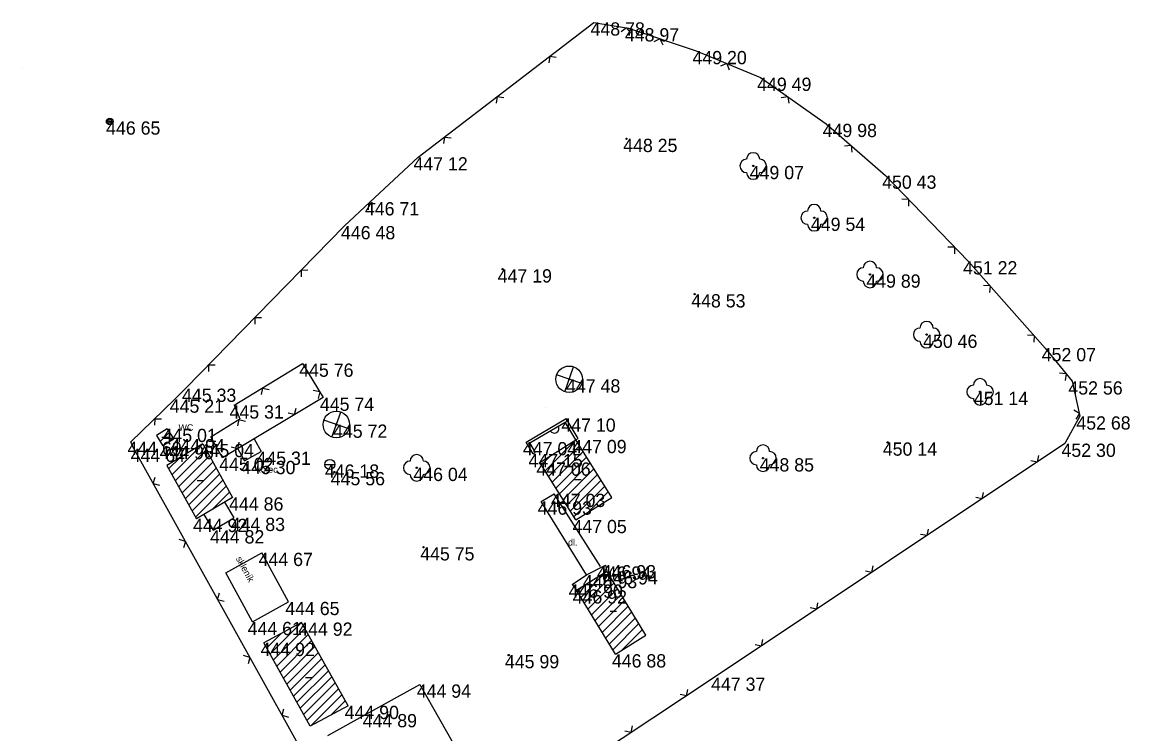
# Model space of a CAD drawing. Extents: x -554123 to -553118, y -1076825 to -1073672.
# Drawn here: x -553887.3 to -553803.8, y -1073725.5 to -1073671.8 of the extents above; entities that cross this region are included whole.
import ezdxf

# ---------------------------------------------------------------- set-up
doc = ezdxf.new("R2010")
doc.units = 0
for name, color, linetype in [('1', 7, 'Continuous'), ('12', 7, 'Continuous'), ('14', 7, 'Continuous'), ('17', 7, 'Continuous'), ('18', 7, 'Continuous'), ('20', 7, 'Continuous'), ('32', 7, 'Continuous'), ('34', 7, 'Continuous'), ('47', 7, 'Continuous'), ('52', 7, 'Continuous'), ('6', 7, 'Continuous')]:
    doc.layers.add(name, color=color, linetype=linetype)

# ---------------------------------------------------------------- blocks, each defined once
blk = doc.blocks.new('POINT_DISPLAY')
blk.add_line((0, 0), (0, 0))
blk = doc.blocks.new('SLB')
at = {"layer": '20'}
for radius in [0.25, 0.158, 0.05]:
    blk.add_circle((0, 0), radius, dxfattribs=at)
blk = doc.blocks.new('ST')
at = {"layer": '1'}
blk.add_line((-0.375, 0), (0.375, 0), dxfattribs=at)
blk.add_circle((0, 0), 0.375, dxfattribs=at)
blk = doc.blocks.new('T')
at = {"layer": '6'}
blk.add_circle((0, 0), 0.05, dxfattribs=at)
blk = doc.blocks.new('STJ')
at = {"layer": '34'}
for p, q in [((-0.327, -0.945), (0.327, 0.945)), ((0.945, -0.327), (-0.945, 0.327))]:
    blk.add_line(p, q, dxfattribs=at)
for radius in [1, 0.0496]:
    blk.add_circle((0, 0), radius, dxfattribs=at)
blk = doc.blocks.new('STL')
at = {"layer": '34'}
blk.add_circle((0, 0), 0.05, dxfattribs=at)
for centre, start, end in [((0, 0.5), 0, 180), ((-0.5, 0), 90, 270), ((0.5, 0), 270, 90), ((0, -0.5), 180, 0)]:
    blk.add_arc(centre, 0.5, start, end, dxfattribs=at)
blk = doc.blocks.new('BN')
at = {"layer": '47'}
blk.add_line((-0.25, 0), (0.25, 0), dxfattribs=at)

msp = doc.modelspace()

# ---------------------------------------------------------------- linework, layer by layer
at = {"layer": '12'}
for p, q in [((-553857.47, -1073681.97), (-553844.23, -1073671.8)), ((-553844.23, -1073671.8), (-553841.63, -1073672.24)), ((-553841.765, -1073672.217), (-553842.173, -1073672.507)), ((-553841.765, -1073672.217), (-553841.475, -1073672.625)), ((-553841.63, -1073672.24), (-553836.53, -1073673.96)), ((-553839.261, -1073673.039), (-553839.71, -1073673.261)), ((-553839.261, -1073673.039), (-553839.039, -1073673.487)), ((-553836.53, -1073673.96), (-553831.66, -1073675.97)), ((-553847.557, -1073674.355), (-553847.622, -1073674.852)), ((-553847.557, -1073674.355), (-553847.061, -1073674.421)), ((-553834.219, -1073674.914), (-553834.681, -1073675.106)), ((-553834.219, -1073674.914), (-553834.027, -1073675.376)), ((-553831.66, -1073675.97), (-553826.71, -1073679.45)), ((-553851.522, -1073677.401), (-553851.587, -1073677.898)), ((-553851.522, -1073677.401), (-553851.026, -1073677.466)), ((-553829.615, -1073677.408), (-553830.108, -1073677.494)), ((-553829.615, -1073677.408), (-553829.529, -1073677.901)), ((-553826.71, -1073679.45), (-553822.25, -1073683.35)), ((-553855.487, -1073680.447), (-553855.552, -1073680.943)), ((-553855.487, -1073680.447), (-553854.991, -1073680.512)), ((-553824.828, -1073681.096), (-553825.328, -1073681.129)), ((-553824.828, -1073681.096), (-553824.795, -1073681.595)), ((-553861.12, -1073685.36), (-553857.47, -1073681.97)), ((-553822.25, -1073683.35), (-553816.03, -1073689.81)), ((-553863.04, -1073687.16), (-553861.12, -1073685.36)), ((-553861.216, -1073685.45), (-553861.232, -1073685.951)), ((-553861.216, -1073685.45), (-553860.716, -1073685.466)), ((-553820.516, -1073685.151), (-553821.017, -1073685.141)), ((-553820.516, -1073685.151), (-553820.525, -1073685.651)), ((-553875.02, -1073699.42), (-553863.04, -1073687.16)), ((-553817.048, -1073688.753), (-553817.549, -1073688.743)), ((-553817.048, -1073688.753), (-553817.057, -1073689.253)), ((-553816.03, -1073689.81), (-553810.21, -1073696.36)), ((-553866.284, -1073690.48), (-553865.783, -1073690.474)), ((-553866.284, -1073690.48), (-553866.278, -1073690.98)), ((-553814.369, -1073691.679), (-553814.869, -1073691.649)), ((-553814.369, -1073691.679), (-553814.399, -1073692.179)), ((-553869.778, -1073694.056), (-553869.278, -1073694.05)), ((-553869.778, -1073694.056), (-553869.773, -1073694.556)), ((-553811.048, -1073695.417), (-553811.548, -1073695.387)), ((-553811.048, -1073695.417), (-553811.078, -1073695.916)), ((-553810.21, -1073696.36), (-553808.19, -1073698.87)), ((-553873.273, -1073697.632), (-553872.772, -1073697.626)), ((-553873.273, -1073697.632), (-553873.267, -1073698.133)), ((-553871.33, -1073700.68), (-553866.18, -1073697.53)), ((-553866.18, -1073697.53), (-553864.64, -1073700.1)), ((-553808.643, -1073698.308), (-553809.14, -1073698.254)), ((-553808.643, -1073698.308), (-553808.696, -1073698.805)), ((-553808.19, -1073698.87), (-553807.59, -1073701.51)), ((-553875.84, -1073700.24), (-553875.02, -1073699.42)), ((-553869.197, -1073699.376), (-553869.315, -1073699.862)), ((-553869.197, -1073699.376), (-553868.711, -1073699.493)), ((-553864.895, -1073699.674), (-553865.381, -1073699.553)), ((-553864.895, -1073699.674), (-553865.017, -1073700.16)), ((-553879.12, -1073703.43), (-553875.84, -1073700.24)), ((-553864.64, -1073700.1), (-553872.22, -1073704.64)), ((-553871.33, -1073700.68), (-553870.91, -1073701.71)), ((-553866.785, -1073701.385), (-553867.27, -1073701.263)), ((-553866.785, -1073701.385), (-553866.663, -1073700.899)), ((-553807.59, -1073701.51), (-553808.72, -1073703.57)), ((-553807.636, -1073701.308), (-553808.06, -1073701.041)), ((-553807.636, -1073701.308), (-553807.903, -1073701.731)), ((-553877.328, -1073701.687), (-553877.335, -1073702.188)), ((-553877.328, -1073701.687), (-553876.827, -1073701.694)), ((-553873.11, -1073703.06), (-553870.91, -1073701.71)), ((-553870.979, -1073701.752), (-553871.096, -1073702.239)), ((-553870.979, -1073701.752), (-553870.492, -1073701.869)), ((-553849.34, -1073703.45), (-553846.32, -1073701.67)), ((-553849.064, -1073703.52), (-553846.39, -1073701.944)), ((-553845.595, -1073703.293), (-553846.39, -1073701.944)), ((-553846.218, -1073701.842), (-553846.32, -1073701.67)), ((-553845.423, -1073703.192), (-553846.32, -1073701.67)), ((-553872.22, -1073704.64), (-553873.11, -1073703.06)), ((-553845.595, -1073703.293), (-553845.423, -1073703.192)), ((-553878.9, -1073703.95), (-553879.12, -1073703.43)), ((-553878.9, -1073703.95), (-553863.75, -1073731.22)), ((-553871.074, -1073703.954), (-553871.56, -1073703.832)), ((-553871.074, -1073703.954), (-553870.952, -1073703.468)), ((-553848.8, -1073704.35), (-553849.34, -1073703.45)), ((-553848.628, -1073704.247), (-553849.064, -1073703.52)), ((-553808.72, -1073703.57), (-553835.15, -1073721.21)), ((-553848.8, -1073704.35), (-553848.628, -1073704.247)), ((-553810.799, -1073704.958), (-553811.29, -1073704.86)), ((-553810.799, -1073704.958), (-553810.701, -1073704.467)), ((-553877.443, -1073706.572), (-553877.306, -1073706.091)), ((-553877.443, -1073706.572), (-553876.962, -1073706.71)), ((-553814.958, -1073707.734), (-553814.86, -1073707.243)), ((-553814.958, -1073707.734), (-553815.449, -1073707.636)), ((-553819.117, -1073710.509), (-553819.608, -1073710.411)), ((-553819.117, -1073710.509), (-553819.019, -1073710.018)), ((-553875.015, -1073710.943), (-553875.496, -1073710.806)), ((-553875.015, -1073710.943), (-553875.152, -1073711.425)), ((-553823.276, -1073713.285), (-553823.767, -1073713.187)), ((-553823.276, -1073713.285), (-553823.178, -1073712.794)), ((-553872.587, -1073715.314), (-553872.449, -1073714.833)), ((-553872.587, -1073715.314), (-553872.105, -1073715.452)), ((-553827.435, -1073716.061), (-553827.337, -1073715.57)), ((-553827.435, -1073716.061), (-553827.926, -1073715.963)), ((-553831.593, -1073718.836), (-553832.084, -1073718.738)), ((-553831.593, -1073718.836), (-553831.495, -1073718.345)), ((-553870.158, -1073719.685), (-553870.64, -1073719.547)), ((-553870.158, -1073719.685), (-553870.296, -1073720.166)), ((-553835.15, -1073721.21), (-553850.11, -1073731.1)), ((-553837.235, -1073722.589), (-553837.135, -1073722.098)), ((-553837.235, -1073722.589), (-553837.726, -1073722.489)), ((-553867.73, -1073724.056), (-553867.593, -1073723.574)), ((-553867.73, -1073724.056), (-553867.249, -1073724.193)), ((-553841.406, -1073725.346), (-553841.306, -1073724.856)), ((-553841.406, -1073725.346), (-553841.897, -1073725.246))]:
    msp.add_line(p, q, dxfattribs=at)
msp.add_arc((-553847.212, -1073702.428), 0.35, 210.51421, 30.51421, dxfattribs=at)
at = {"layer": '14'}
for p, q in [((-553876.38, -1073702.45), (-553877.19, -1073702.96)), ((-553877.19, -1073702.96), (-553876.71, -1073703.74)), ((-553875.9, -1073703.23), (-553876.71, -1073703.74)), ((-553876.38, -1073702.45), (-553875.9, -1073703.23)), ((-553873.7, -1073703.59), (-553876.42, -1073705.21)), ((-553873.7, -1073703.59), (-553871.47, -1073707.62)), ((-553848.3, -1073704.99), (-553845.59, -1073703.29)), ((-553842.88, -1073707.62), (-553845.59, -1073703.29)), ((-553876.42, -1073705.21), (-553874.19, -1073709.24)), ((-553845.59, -1073709.32), (-553848.3, -1073704.99)), ((-553871.47, -1073707.62), (-553874.19, -1073709.24)), ((-553845.59, -1073709.32), (-553842.88, -1073707.62)), ((-553845.55, -1073714.63), (-553843.24, -1073713.19)), ((-553840.3, -1073718.01), (-553843.24, -1073713.19)), ((-553842.61, -1073719.45), (-553845.55, -1073714.63)), ((-553866.26, -1073717.06), (-553869.1, -1073718.59)), ((-553862.76, -1073723.34), (-553866.26, -1073717.06)), ((-553842.61, -1073719.45), (-553840.3, -1073718.01)), ((-553865.6, -1073724.87), (-553869.1, -1073718.59)), ((-553862.76, -1073723.34), (-553865.6, -1073724.87))]:
    msp.add_line(p, q, dxfattribs=at)
at = {"layer": '17'}
for p, q in [((-553848.19, -1073707.93), (-553847.21, -1073707.35)), ((-553843.74, -1073712.83), (-553847.21, -1073707.35)), ((-553844.78, -1073713.47), (-553848.19, -1073707.93)), ((-553861.4, -1073723.96), (-553857.34, -1073721.73)), ((-553857.34, -1073721.73), (-553854.38, -1073726.95)), ((-553864.29, -1073725.58), (-553861.4, -1073723.96))]:
    msp.add_line(p, q, dxfattribs=at)
at = {"layer": '18'}
for p, q in [((-553869.833, -1073703.21), (-553869.3, -1073704.17)), ((-553871.071, -1073703.952), (-553870.56, -1073704.87)), ((-553870.56, -1073704.87), (-553869.3, -1073704.17)), ((-553872.066, -1073707.975), (-553871.36, -1073709.16)), ((-553873.631, -1073708.907), (-553872.92, -1073710.1)), ((-553872.92, -1073710.1), (-553871.36, -1073709.16)), ((-553871.98, -1073713.31), (-553869.25, -1073711.8)), ((-553867.24, -1073715.5), (-553869.25, -1073711.8)), ((-553844.78, -1073713.47), (-553843.36, -1073712.73)), ((-553843.36, -1073712.73), (-553843.24, -1073713.19)), ((-553869.97, -1073717.01), (-553871.98, -1073713.31)), ((-553845.86, -1073714.19), (-553844.78, -1073713.47)), ((-553845.86, -1073714.19), (-553845.55, -1073714.63)), ((-553869.97, -1073717.01), (-553867.24, -1073715.5))]:
    msp.add_line(p, q, dxfattribs=at)
at = {"layer": '32'}
for p, q in [((-553876.921, -1073703.398), (-553876.225, -1073702.702)), ((-553876.294, -1073703.478), (-553875.956, -1073703.14)), ((-553876.028, -1073705.918), (-553873.7, -1073703.59)), ((-553875.776, -1073706.373), (-553873.448, -1073704.045)), ((-553847.911, -1073705.611), (-553845.59, -1073703.29)), ((-553847.639, -1073706.046), (-553845.318, -1073703.725)), ((-553876.28, -1073705.463), (-553875.448, -1073704.631)), ((-553875.524, -1073706.829), (-553873.196, -1073704.5)), ((-553848.183, -1073705.176), (-553847.487, -1073704.48)), ((-553847.367, -1073706.481), (-553845.046, -1073704.16)), ((-553847.095, -1073706.916), (-553844.773, -1073704.595)), ((-553875.272, -1073707.284), (-553872.944, -1073704.956)), ((-553875.021, -1073707.739), (-553872.692, -1073705.411)), ((-553846.822, -1073707.351), (-553844.501, -1073705.03)), ((-553846.55, -1073707.786), (-553844.229, -1073705.465)), ((-553874.769, -1073708.194), (-553872.441, -1073705.866)), ((-553874.517, -1073708.649), (-553872.189, -1073706.321)), ((-553846.278, -1073708.221), (-553843.957, -1073705.899)), ((-553846.006, -1073708.656), (-553843.685, -1073706.334)), ((-553874.265, -1073709.105), (-553871.937, -1073706.776)), ((-553872.961, -1073708.508), (-553871.685, -1073707.232)), ((-553845.734, -1073709.09), (-553843.412, -1073706.769)), ((-553844.694, -1073708.758), (-553843.14, -1073707.204)), ((-553845.22, -1073715.17), (-553843.24, -1073713.19)), ((-553844.952, -1073715.61), (-553842.972, -1073713.629)), ((-553844.685, -1073716.049), (-553842.704, -1073714.068)), ((-553845.488, -1073714.731), (-553845.117, -1073714.36)), ((-553844.417, -1073716.488), (-553842.436, -1073714.508)), ((-553844.149, -1073716.927), (-553842.168, -1073714.947)), ((-553843.881, -1073717.366), (-553841.901, -1073715.386)), ((-553843.613, -1073717.806), (-553841.633, -1073715.825)), ((-553843.345, -1073718.245), (-553841.365, -1073716.264)), ((-553868.631, -1073719.431), (-553866.26, -1073717.06)), ((-553843.077, -1073718.684), (-553841.097, -1073716.704)), ((-553842.809, -1073719.123), (-553840.829, -1073717.143)), ((-553868.884, -1073718.977), (-553867.793, -1073717.886)), ((-553868.378, -1073719.885), (-553866.007, -1073717.514)), ((-553868.125, -1073720.339), (-553865.754, -1073717.968)), ((-553842.129, -1073719.15), (-553840.561, -1073717.582)), ((-553867.872, -1073720.793), (-553865.501, -1073718.422)), ((-553867.619, -1073721.247), (-553865.248, -1073718.876)), ((-553867.366, -1073721.701), (-553864.995, -1073719.33)), ((-553867.113, -1073722.155), (-553864.742, -1073719.784)), ((-553866.86, -1073722.61), (-553864.489, -1073720.238)), ((-553866.607, -1073723.064), (-553864.236, -1073720.692)), ((-553866.354, -1073723.518), (-553863.983, -1073721.146)), ((-553866.101, -1073723.972), (-553863.729, -1073721.601)), ((-553865.848, -1073724.426), (-553863.476, -1073722.055)), ((-553865.567, -1073724.852), (-553863.223, -1073722.509)), ((-553864.034, -1073724.026), (-553862.97, -1073722.963))]:
    msp.add_line(p, q, dxfattribs=at)

# ---------------------------------------------------------------- block references
at = {"layer": '1'}
for name, p in [('POINT_DISPLAY', (-553844.23, -1073671.8)), ('POINT_DISPLAY', (-553841.63, -1073672.24)), ('POINT_DISPLAY', (-553836.53, -1073673.96)), ('POINT_DISPLAY', (-553887.32, -1073675.17)), ('POINT_DISPLAY', (-553831.66, -1073675.97)), ('POINT_DISPLAY', (-553880.72, -1073679.27)), ('POINT_DISPLAY', (-553826.71, -1073679.45)), ('POINT_DISPLAY', (-553841.77, -1073680.58)), ('POINT_DISPLAY', (-553857.47, -1073681.97)), ('POINT_DISPLAY', (-553832.22, -1073682.63)), ('POINT_DISPLAY', (-553822.25, -1073683.35)), ('POINT_DISPLAY', (-553861.12, -1073685.36)), ('POINT_DISPLAY', (-553827.62, -1073686.53)), ('POINT_DISPLAY', (-553863.04, -1073687.16)), ('POINT_DISPLAY', (-553816.03, -1073689.81)), ('POINT_DISPLAY', (-553851.11, -1073690.42)), ('POINT_DISPLAY', (-553823.42, -1073690.81)), ('POINT_DISPLAY', (-553836.64, -1073692.3)), ('POINT_DISPLAY', (-553819.15, -1073695.35)), ('POINT_DISPLAY', (-553810.21, -1073696.36)), ('POINT_DISPLAY', (-553866.18, -1073697.53)), ('POINT_DISPLAY', (-553846.09, -1073698.72)), ('POINT_DISPLAY', (-553808.19, -1073698.87)), ('POINT_DISPLAY', (-553875.02, -1073699.42)), ('POINT_DISPLAY', (-553815.12, -1073699.66)), ('POINT_DISPLAY', (-553875.84, -1073700.24)), ('POINT_DISPLAY', (-553871.33, -1073700.68)), ('POINT_DISPLAY', (-553864.64, -1073700.1)), ('POINT_DISPLAY', (-553847.87, -1073700.82)), ('POINT_DISPLAY', (-553807.59, -1073701.51)), ('POINT_DISPLAY', (-553870.91, -1073701.71)), ('POINT_DISPLAY', (-553863.64, -1073702.13)), ('POINT_DISPLAY', (-553846.32, -1073701.67)), ('POINT_DISPLAY', (-553876.38, -1073702.45)), ('POINT_DISPLAY', (-553875.9, -1073703.23)), ('POINT_DISPLAY', (-553873.11, -1073703.06)), ('POINT_DISPLAY', (-553879.12, -1073703.43)), ('POINT_DISPLAY', (-553878.9, -1073703.95)), ('POINT_DISPLAY', (-553876.71, -1073703.74)), ('POINT_DISPLAY', (-553873.7, -1073703.59)), ('POINT_DISPLAY', (-553849.34, -1073703.45)), ('POINT_DISPLAY', (-553845.59, -1073703.29)), ('POINT_DISPLAY', (-553822.09, -1073703.48)), ('POINT_DISPLAY', (-553808.72, -1073703.57)), ('POINT_DISPLAY', (-553872.22, -1073704.64)), ('POINT_DISPLAY', (-553870.56, -1073704.87)), ('POINT_DISPLAY', (-553869.3, -1073704.17)), ('ST', (-553864.13, -1073705.14)), ('POINT_DISPLAY', (-553848.8, -1073704.35)), ('POINT_DISPLAY', (-553831.48, -1073704.67)), ('POINT_DISPLAY', (-553864.13, -1073705.14)), ('POINT_DISPLAY', (-553863.8, -1073705.71)), ('POINT_DISPLAY', (-553857.58, -1073705.39)), ('POINT_DISPLAY', (-553848.3, -1073704.99)), ('POINT_DISPLAY', (-553847.21, -1073707.35)), ('POINT_DISPLAY', (-553871.47, -1073707.62)), ('POINT_DISPLAY', (-553848.19, -1073707.93)), ('POINT_DISPLAY', (-553874.19, -1073709.24)), ('POINT_DISPLAY', (-553871.36, -1073709.16)), ('POINT_DISPLAY', (-553845.59, -1073709.32)), ('POINT_DISPLAY', (-553872.92, -1073710.1)), ('POINT_DISPLAY', (-553857.07, -1073711.38)), ('POINT_DISPLAY', (-553869.25, -1073711.8)), ('POINT_DISPLAY', (-553843.74, -1073712.83)), ('POINT_DISPLAY', (-553843.36, -1073712.73)), ('POINT_DISPLAY', (-553843.24, -1073713.19)), ('POINT_DISPLAY', (-553844.78, -1073713.47)), ('POINT_DISPLAY', (-553845.86, -1073714.19)), ('POINT_DISPLAY', (-553845.55, -1073714.63)), ('POINT_DISPLAY', (-553867.24, -1073715.5)), ('POINT_DISPLAY', (-553869.97, -1073717.01)), ('POINT_DISPLAY', (-553866.26, -1073717.06)), ('POINT_DISPLAY', (-553869.1, -1073718.59)), ('POINT_DISPLAY', (-553850.66, -1073719.51)), ('POINT_DISPLAY', (-553842.61, -1073719.45)), ('POINT_DISPLAY', (-553835.15, -1073721.21)), ('POINT_DISPLAY', (-553857.34, -1073721.73)), ('POINT_DISPLAY', (-553862.76, -1073723.34)), ('POINT_DISPLAY', (-553861.4, -1073723.96))]:
    msp.add_blockref(name, p, dxfattribs=at)
at = {"layer": '20'}
msp.add_blockref('SLB', (-553880.72, -1073679.27), dxfattribs=at)
at = {"layer": '32'}
for p in [(-553877.19, -1073702.96), (-553873.7, -1073703.59), (-553845.59, -1073703.29), (-553843.24, -1073713.19), (-553866.26, -1073717.06)]:
    msp.add_blockref('POINT_DISPLAY', p, dxfattribs=at)
at = {"layer": '34'}
for name, p in [('STL', (-553832.22, -1073682.63)), ('STL', (-553827.62, -1073686.53)), ('STL', (-553823.42, -1073690.81)), ('STL', (-553819.15, -1073695.35)), ('STJ', (-553846.09, -1073698.72)), ('STL', (-553815.12, -1073699.66)), ('STJ', (-553863.64, -1073702.13)), ('STL', (-553831.48, -1073704.67)), ('STL', (-553857.58, -1073705.39))]:
    msp.add_blockref(name, p, dxfattribs=at)
at = {"layer": '47'}
for p in [(-553876.548, -1073703.088), (-553873.882, -1073706.345), (-553845.427, -1073706.27), (-553842.761, -1073716.198), (-553865.709, -1073721.21)]:
    msp.add_blockref('BN', p, dxfattribs=at)
at = {"layer": '6'}
for p in [(-553841.77, -1073680.58), (-553851.11, -1073690.42), (-553836.64, -1073692.3), (-553822.09, -1073703.48), (-553863.8, -1073705.71), (-553857.07, -1073711.38), (-553850.66, -1073719.51)]:
    msp.add_blockref('T', p, dxfattribs=at)

# ---------------------------------------------------------------- texts
at = {"layer": '52'}
for s, p in [('WC', (-553875.534, -1073702.608)), ('kotec', (-553869.659, -1073705.768)), ('dl.', (-553846.172, -1073711.262))]:
    msp.add_text(s, height=0.5, dxfattribs=at).set_placement(p)
msp.add_text('skleník', height=0.5, rotation=298.51272, dxfattribs=at).set_placement((-553871.227, -1073712.24))
at = {"layer": '6'}
for s, p in [('448 78 ', (-553844.478, -1073672.8)), ('448 97 ', (-553841.89, -1073673.24)), ('449 20 ', (-553836.794, -1073674.96)), ('449 49 ', (-553831.922, -1073676.97)), ('446 65 ', (-553880.994, -1073680.27)), ('449 98 ', (-553826.984, -1073680.45)), ('448 25 ', (-553842.02, -1073681.58)), ('447 12 ', (-553857.827, -1073682.97)), ('449 07 ', (-553832.482, -1073683.63)), ('450 43 ', (-553822.502, -1073684.35)), ('446 71 ', (-553861.487, -1073686.36)), ('449 54 ', (-553827.87, -1073687.53)), ('446 48 ', (-553863.29, -1073688.16)), ('451 22 ', (-553816.401, -1073690.81)), ('447 19 ', (-553851.479, -1073691.42)), ('449 89 ', (-553823.694, -1073691.81)), ('448 53 ', (-553836.89, -1073693.3)), ('450 46 ', (-553819.414, -1073696.35)), ('452 07 ', (-553810.472, -1073697.36)), ('445 76 ', (-553866.44, -1073698.53)), ('447 48 ', (-553846.326, -1073699.72)), ('452 56 ', (-553808.464, -1073699.87)), ('445 33 ', (-553875.27, -1073700.42)), ('451 14 ', (-553815.588, -1073700.66)), ('445 21 ', (-553876.197, -1073701.24)), ('445 31 ', (-553871.687, -1073701.68)), ('445 74 ', (-553864.876, -1073701.1)), ('452 68 ', (-553807.864, -1073702.51)), ('445 72 ', (-553863.888, -1073703.13)), ('447 10 ', (-553846.679, -1073702.67)), ('445 01 ', (-553876.739, -1073703.45)), ('444 94 ', (-553876.138, -1073704.23)), ('444 69 ', (-553879.382, -1073704.43)), ('444 64 ', (-553879.138, -1073704.95)), ('444 90 ', (-553876.962, -1073704.74)), ('445 04 ', (-553873.94, -1073704.59)), ('447 04 ', (-553849.578, -1073704.45)), ('447 09 ', (-553845.852, -1073704.29)), ('450 14 ', (-553822.451, -1073704.48)), ('452 30 ', (-553808.984, -1073704.57)), ('445 02 ', (-553872.472, -1073705.64)), ('445 30 ', (-553870.812, -1073705.87)), ('445 31 ', (-553869.657, -1073705.17)), ('447 15 ', (-553849.157, -1073705.35)), ('448 85 ', (-553831.73, -1073705.67)), ('446 18 ', (-553864.501, -1073706.14)), ('445 56 ', (-553864.062, -1073706.71)), ('446 04 ', (-553857.832, -1073706.39)), ('447 06 ', (-553848.562, -1073705.99)), ('447 03 ', (-553847.46, -1073708.35)), ('444 86 ', (-553871.72, -1073708.62)), ('446 93 ', (-553848.464, -1073708.93)), ('444 92 ', (-553874.44, -1073710.24)), ('444 83 ', (-553871.598, -1073710.16)), ('447 05 ', (-553845.84, -1073710.32)), ('444 82 ', (-553873.158, -1073711.1)), ('445 75 ', (-553857.318, -1073712.38)), ('444 67 ', (-553869.498, -1073712.8)), ('446 94 ', (-553844.002, -1073713.83)), ('446 93 ', (-553843.634, -1073713.73)), ('446 94 ', (-553843.502, -1073714.19)), ('446 93 ', (-553845.054, -1073714.47)), ('446 90 ', (-553846.136, -1073715.19)), ('446 92 ', (-553845.824, -1073715.63)), ('444 65 ', (-553867.49, -1073716.5)), ('444 61 ', (-553870.327, -1073718.01)), ('444 92 ', (-553866.51, -1073718.06)), ('444 92 ', (-553869.35, -1073719.59)), ('445 99 ', (-553850.934, -1073720.51)), ('446 88 ', (-553842.872, -1073720.45)), ('447 37 ', (-553835.396, -1073722.21)), ('444 94 ', (-553857.578, -1073722.73)), ('444 90 ', (-553863.012, -1073724.34)), ('444 89 ', (-553861.65, -1073724.96))]:
    msp.add_text(s, height=1, dxfattribs=at).set_placement(p)

doc.saveas('drawing.dxf')
